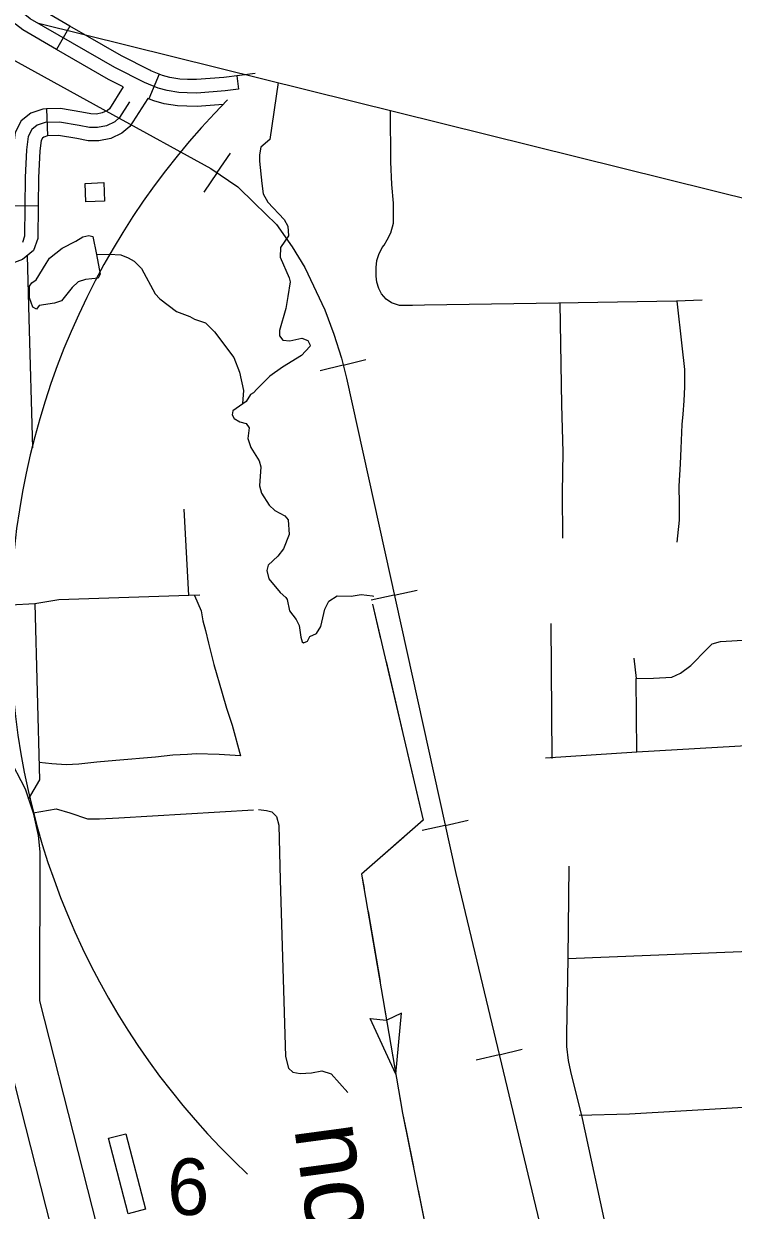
# Model space of a CAD drawing. Extents: x 1671357 to 13005564, y 567358 to 14261451.
# Drawn here: x 12758300.259 to 12758301.586, y 14259942.041 to 14259944.26 of the extents above; entities that cross this region are included whole.
import ezdxf

# ---------------------------------------------------------------- set-up
doc = ezdxf.new("R2010")
doc.units = 0
for name, color, linetype in [('15', 7, 'Continuous'), ('31', 7, 'Continuous'), ('32', 7, 'Continuous'), ('35', 7, 'Continuous'), ('40', 7, 'Continuous'), ('43', 7, 'Continuous'), ('5', 7, 'Continuous'), ('56', 7, 'Continuous'), ('63', 7, 'Continuous'), ('Default', 7, 'Continuous')]:
    doc.layers.add(name, color=color, linetype=linetype)

msp = doc.modelspace()

# ---------------------------------------------------------------- linework, layer by layer
at = {"layer": '15'}
for points in [[(12758299.593, 14259943.9275), (12758299.6236, 14259943.8747), (12758299.6719, 14259943.806), (12758299.8204, 14259943.6294), (12758299.8655, 14259943.5569), (12758300.0827, 14259943.1633), (12758300.2306, 14259942.8901), (12758300.2619, 14259942.8294), (12758300.2768, 14259942.7845), (12758300.2866, 14259942.742), (12758300.2893, 14259942.7116), (12758300.2887, 14259942.4326), (12758300.6474, 14259941.0247)], [(12758300.5675, 14259941.0004), (12758300.2052, 14259942.4222), (12758300.2058, 14259942.7081), (12758300.204, 14259942.7289), (12758300.1964, 14259942.7619), (12758300.1847, 14259942.7969), (12758300.1568, 14259942.8511), (12758300.0094, 14259943.1233), (12758299.7935, 14259943.5146), (12758299.7527, 14259943.5802), (12758299.6057, 14259943.7551), (12758299.5532, 14259943.8296), (12758299.5425, 14259943.8482), (12758299.5157, 14259943.9046)]]:
    msp.add_lwpolyline(points, dxfattribs=at)
at = {"layer": '31'}
for points in [[(12758301.2453, 14259943.1384), (12758301.2468, 14259942.8858)], [(12758301.4006, 14259943.0738), (12758301.4045, 14259943.0354), (12758301.4372, 14259943.0364), (12758301.4715, 14259943.0382), (12758301.4876, 14259943.0453), (12758301.507, 14259943.0599), (12758301.5378, 14259943.0907), (12758301.5467, 14259943.1004), (12758301.5625, 14259943.1048), (12758301.7611, 14259943.1166), (12758301.7694, 14259943.117), (12758301.7785, 14259943.115), (12758301.7847, 14259943.1113), (12758301.7892, 14259943.0997), (12758301.794, 14259942.9863), (12758302.0259, 14259942.9248)], [(12758301.2352, 14259942.8874), (12758301.4057, 14259942.8987), (12758301.4045, 14259943.0354)], [(12758301.4057, 14259942.8987), (12758301.7828, 14259942.9205), (12758301.7937, 14259942.924), (12758301.7951, 14259942.9294), (12758301.7954, 14259942.9391), (12758301.794, 14259942.9863)], [(12758300.2768, 14259942.7845), (12758300.3202, 14259942.792), (12758300.3459, 14259942.7844), (12758300.3785, 14259942.7734), (12758300.4012, 14259942.7734), (12758300.4372, 14259942.7752), (12758300.6892, 14259942.7902)], [(12758301.2791, 14259942.6845), (12758301.277, 14259942.5122), (12758301.2743, 14259942.3704)], [(12758301.277, 14259942.5122), (12758302.0346, 14259942.5427)], [(12758301.2743, 14259942.3704), (12758301.2746, 14259942.3478), (12758301.2777, 14259942.3215), (12758301.2816, 14259942.3005), (12758301.3037, 14259942.213), (12758301.3492, 14259942.0021)]]:
    msp.add_lwpolyline(points, dxfattribs=at)
at = {"layer": '32'}
for p, q in [((12758300.3459, 14259944.255), (12758300.3209, 14259944.2116)), ((12758300.5126, 14259944.1655), (12758300.4936, 14259944.1191)), ((12758300.6577, 14259944.1622), (12758300.661, 14259944.1373)), ((12758300.3022, 14259944.1003), (12758300.3037, 14259944.0502)), ((12758300.2366, 14259943.92), (12758300.2867, 14259943.9194))]:
    msp.add_line(p, q, dxfattribs=at)
for points in [[(12758300.5653, 14259944.1306), (12758300.5492, 14259944.131), (12758300.5274, 14259944.1345), (12758300.5108, 14259944.1391), (12758300.485, 14259944.1498), (12758300.43, 14259944.1776), (12758300.2715, 14259944.269), (12758300.2612, 14259944.2769), (12758300.2535, 14259944.2857), (12758300.2434, 14259944.3027), (12758300.2363, 14259944.3195), (12758300.2335, 14259944.4179), (12758300.2336, 14259944.4531), (12758300.2308, 14259944.4808), (12758300.225, 14259944.514), (12758300.2152, 14259944.5478), (12758300.1987, 14259944.5997), (12758300.1349, 14259944.7499)], [(12758300.3209, 14259944.2116), (12758300.2576, 14259944.2481), (12758300.244, 14259944.2585), (12758300.2331, 14259944.2708), (12758300.221, 14259944.2914), (12758300.2114, 14259944.3141), (12758300.2101, 14259944.3609)], [(12758300.3459, 14259944.255), (12758300.2855, 14259944.2899), (12758300.2783, 14259944.2953), (12758300.2738, 14259944.3005), (12758300.2658, 14259944.3139), (12758300.2612, 14259944.3248), (12758300.2601, 14259944.3624)], [(12758300.4974, 14259944.1717), (12758300.4954, 14259944.1725), (12758300.442, 14259944.1996), (12758300.3459, 14259944.255)], [(12758300.4455, 14259944.1417), (12758300.4181, 14259944.1555), (12758300.3209, 14259944.2116)], [(12758300.6924, 14259944.1667), (12758300.6337, 14259944.159), (12758300.5824, 14259944.1552), (12758300.5659, 14259944.1556), (12758300.5515, 14259944.156), (12758300.5327, 14259944.159), (12758300.519, 14259944.1628), (12758300.4974, 14259944.1717)], [(12758300.4455, 14259944.1417), (12758300.4198, 14259944.1008), (12758300.4159, 14259944.0976), (12758300.4061, 14259944.0929), (12758300.3953, 14259944.0907), (12758300.3848, 14259944.0909), (12758300.3678, 14259944.0941), (12758300.3281, 14259944.101), (12758300.3022, 14259944.1003)], [(12758300.661, 14259944.1373), (12758300.6363, 14259944.1341), (12758300.583, 14259944.1301), (12758300.5653, 14259944.1306)], [(12758300.4573, 14259944.1134), (12758300.4388, 14259944.0841), (12758300.4295, 14259944.0763), (12758300.4141, 14259944.069), (12758300.3976, 14259944.0656), (12758300.3822, 14259944.0659), (12758300.3633, 14259944.0695), (12758300.3263, 14259944.0759), (12758300.2996, 14259944.0751), (12758300.2848, 14259944.0701), (12758300.2745, 14259944.062), (12758300.2677, 14259944.0486), (12758300.2644, 14259944.024), (12758300.2623, 14259943.972), (12758300.2609, 14259943.8623), (12758300.2568, 14259943.8508)], [(12758300.4912, 14259944.1201), (12758300.4579, 14259944.0674), (12758300.4431, 14259944.0551), (12758300.4221, 14259944.045), (12758300.3998, 14259944.0405), (12758300.3796, 14259944.0409), (12758300.3589, 14259944.0448), (12758300.3245, 14259944.0508), (12758300.3037, 14259944.0502)], [(12758300.6321, 14259944.1087), (12758300.5836, 14259944.1051), (12758300.5646, 14259944.1056), (12758300.547, 14259944.1061), (12758300.522, 14259944.11), (12758300.5026, 14259944.1154), (12758300.4912, 14259944.1201)], [(12758300.3021, 14259944.1003), (12758300.2952, 14259944.1001), (12758300.2727, 14259944.0925), (12758300.2547, 14259944.0782), (12758300.2435, 14259944.0562), (12758300.2394, 14259944.0262), (12758300.2373, 14259943.9727), (12758300.2366, 14259943.92)], [(12758301.5283, 14259943.7426), (12758301.4803, 14259943.741), (12758301.2592, 14259943.7371), (12758301.0086, 14259943.7335), (12758300.9863, 14259943.733), (12758300.975, 14259943.7326), (12758300.9623, 14259943.7329), (12758300.9474, 14259943.7377), (12758300.9372, 14259943.7444), (12758300.9285, 14259943.7545), (12758300.9235, 14259943.7644), (12758300.92, 14259943.7767), (12758300.9183, 14259943.7877), (12758300.9187, 14259943.8038), (12758300.9196, 14259943.8172), (12758300.9232, 14259943.8284), (12758300.9298, 14259943.841), (12758300.9333, 14259943.8458), (12758300.939, 14259943.8554), (12758300.9458, 14259943.869), (12758300.9509, 14259943.887), (12758300.9512, 14259943.8987), (12758300.9506, 14259943.9242), (12758300.948, 14259943.9593), (12758300.9459, 14259944.0014), (12758300.9456, 14259944.0973)], [(12758300.3041, 14259944.0502), (12758300.2969, 14259944.0478), (12758300.2943, 14259944.0457), (12758300.292, 14259944.0411), (12758300.2894, 14259944.0219), (12758300.2873, 14259943.9713), (12758300.2867, 14259943.9194)], [(12758300.2867, 14259943.9194), (12758300.2859, 14259943.8578), (12758300.2779, 14259943.8355), (12758300.2569, 14259943.8191), (12758300.2369, 14259943.8115), (12758300.2092, 14259943.8054), (12758300.1544, 14259943.8069)], [(12758301.2675, 14259943.298), (12758301.2669, 14259943.3825), (12758301.2685, 14259943.4589), (12758301.2658, 14259943.5473), (12758301.2628, 14259943.7375)], [(12758301.4813, 14259943.2906), (12758301.4829, 14259943.3024), (12758301.4856, 14259943.3313), (12758301.4855, 14259943.3618), (12758301.4854, 14259943.3953), (12758301.4879, 14259943.4366), (12758301.4886, 14259943.4658), (12758301.491, 14259943.5101), (12758301.4924, 14259943.5299), (12758301.4945, 14259943.5545), (12758301.4959, 14259943.5807), (12758301.4958, 14259943.6135), (12758301.4909, 14259943.6572), (12758301.4811, 14259943.741)], [(12758300.5681, 14259943.1904), (12758300.5595, 14259943.3522)], [(12758300.5887, 14259943.1916), (12758300.5681, 14259943.1904), (12758300.325, 14259943.1824), (12758300.2802, 14259943.1751), (12758300.2345, 14259943.1724)], [(12758300.2802, 14259943.1751), (12758300.2892, 14259942.846), (12758300.2677, 14259942.8096)], [(12758300.5789, 14259943.1907), (12758300.5913, 14259943.1618), (12758300.5946, 14259943.1432), (12758300.5993, 14259943.1253), (12758300.6048, 14259943.1016), (12758300.6148, 14259943.0618), (12758300.6307, 14259943.008), (12758300.6387, 14259942.9798), (12758300.6492, 14259942.948), (12758300.6648, 14259942.8907)], [(12758300.6648, 14259942.8907), (12758300.6251, 14259942.8932), (12758300.582, 14259942.8944), (12758300.5656, 14259942.8932), (12758300.5383, 14259942.8919), (12758300.5057, 14259942.8885), (12758300.4315, 14259942.8819), (12758300.3962, 14259942.8793), (12758300.3623, 14259942.8752), (12758300.3387, 14259942.874), (12758300.3119, 14259942.8761), (12758300.2883, 14259942.8787)], [(12758300.6983, 14259942.7907), (12758300.7134, 14259942.789), (12758300.7235, 14259942.7861), (12758300.7323, 14259942.7778), (12758300.7363, 14259942.7615), (12758300.739, 14259942.6591)], [(12758300.739, 14259942.6591), (12758300.7489, 14259942.3291), (12758300.7544, 14259942.3072), (12758300.7624, 14259942.2995), (12758300.7761, 14259942.297), (12758300.7978, 14259942.2982), (12758300.8167, 14259942.302), (12758300.8346, 14259942.2963), (12758300.8657, 14259942.2617)], [(12758301.3925, 14259942.2218), (12758301.8298, 14259942.2469), (12758301.9275, 14259942.249), (12758302.043, 14259942.2587)], [(12758301.2984, 14259942.2191), (12758301.3925, 14259942.2218)]]:
    msp.add_lwpolyline(points, dxfattribs=at)
at = {"layer": '35'}
for points in [[(12758300.735, 14259944.1496), (12758300.7198, 14259944.0431), (12758300.7027, 14259944.0287), (12758300.7006, 14259944.0148), (12758300.7005, 14259944.0024), (12758300.7049, 14259943.961), (12758300.7074, 14259943.9417), (12758300.7157, 14259943.9263), (12758300.7465, 14259943.8938), (12758300.753, 14259943.8813), (12758300.7545, 14259943.863), (12758300.7397, 14259943.8412), (12758300.7391, 14259943.8234), (12758300.7555, 14259943.7846), (12758300.7575, 14259943.7773), (12758300.753, 14259943.7499), (12758300.7493, 14259943.7273), (12758300.7376, 14259943.6863), (12758300.7377, 14259943.6762), (12758300.7438, 14259943.6678), (12758300.7572, 14259943.6667), (12758300.7797, 14259943.672), (12758300.7909, 14259943.6671), (12758300.7949, 14259943.6589), (12758300.7947, 14259943.6562), (12758300.7787, 14259943.6391), (12758300.7436, 14259943.6175), (12758300.7196, 14259943.6007), (12758300.6956, 14259943.5762), (12758300.6892, 14259943.5693), (12758300.6833, 14259943.5667), (12758300.6752, 14259943.5532), (12758300.6505, 14259943.5358), (12758300.6492, 14259943.5287), (12758300.6531, 14259943.5218), (12758300.6638, 14259943.5155)], [(12758300.3957, 14259943.8279), (12758300.4022, 14259943.7913), (12758300.3989, 14259943.7841), (12758300.3749, 14259943.7817), (12758300.3614, 14259943.7768), (12758300.3502, 14259943.7663), (12758300.3299, 14259943.7416), (12758300.3167, 14259943.7374), (12758300.2882, 14259943.7328), (12758300.2834, 14259943.7262), (12758300.2763, 14259943.7299), (12758300.2705, 14259943.7471), (12758300.2703, 14259943.7689), (12758300.2747, 14259943.7751), (12758300.2828, 14259943.7808), (12758300.3012, 14259943.8111), (12758300.3074, 14259943.8214), (12758300.3314, 14259943.8402), (12758300.3568, 14259943.8534), (12758300.3702, 14259943.8613), (12758300.3811, 14259943.8638), (12758300.3889, 14259943.8618), (12758300.3957, 14259943.8279)], [(12758300.3957, 14259943.8279), (12758300.419, 14259943.8285), (12758300.4411, 14259943.8278), (12758300.4544, 14259943.822), (12758300.466, 14259943.8155), (12758300.4799, 14259943.802), (12758300.5053, 14259943.7548), (12758300.5137, 14259943.7451), (12758300.5451, 14259943.7216), (12758300.5702, 14259943.7123), (12758300.5785, 14259943.7073), (12758300.5845, 14259943.7056), (12758300.5995, 14259943.7002), (12758300.6159, 14259943.6834), (12758300.6526, 14259943.6354), (12758300.6632, 14259943.608), (12758300.6706, 14259943.5738), (12758300.6683, 14259943.5496)], [(12758300.6638, 14259943.5155), (12758300.6756, 14259943.512), (12758300.6809, 14259943.5042), (12758300.6785, 14259943.484), (12758300.6842, 14259943.4675), (12758300.6996, 14259943.4427), (12758300.7031, 14259943.4314), (12758300.7003, 14259943.3954), (12758300.7042, 14259943.3819), (12758300.7182, 14259943.3593), (12758300.7289, 14259943.3497), (12758300.7477, 14259943.3395), (12758300.7537, 14259943.332), (12758300.7559, 14259943.3046), (12758300.7453, 14259943.2781), (12758300.7346, 14259943.2639), (12758300.7166, 14259943.2473), (12758300.714, 14259943.2372), (12758300.718, 14259943.2216), (12758300.7388, 14259943.196), (12758300.7496, 14259943.1871), (12758300.7521, 14259943.1832), (12758300.7566, 14259943.1622), (12758300.769, 14259943.146), (12758300.7745, 14259943.1348), (12758300.7774, 14259943.1129), (12758300.7798, 14259943.1042), (12758300.7825, 14259943.1023), (12758300.7901, 14259943.1053), (12758300.7944, 14259943.1142), (12758300.8069, 14259943.1195), (12758300.8153, 14259943.1326), (12758300.8226, 14259943.1651), (12758300.8297, 14259943.1801), (12758300.8453, 14259943.1901), (12758300.872, 14259943.1896), (12758300.8902, 14259943.1927), (12758300.9117, 14259943.1903), (12758300.9142, 14259943.1896)]]:
    msp.add_lwpolyline(points, dxfattribs=at)
at = {"layer": '40'}
for p, q in [((12758300.621, 14259943.9812), (12758300.6461, 14259944.0175)), ((12758300.621, 14259943.9812), (12758300.5959, 14259943.945)), ((12758300.8566, 14259943.6214), (12758300.8138, 14259943.6107)), ((12758300.8566, 14259943.6214), (12758300.8994, 14259943.6321)), ((12758300.9524, 14259943.1912), (12758300.9954, 14259943.2008)), ((12758300.9524, 14259943.1912), (12758300.9094, 14259943.1817)), ((12758301.0475, 14259942.7609), (12758301.0045, 14259942.7514)), ((12758301.0475, 14259942.7609), (12758301.0906, 14259942.7705)), ((12758301.1487, 14259942.332), (12758301.1058, 14259942.3217)), ((12758301.1487, 14259942.332), (12758301.1915, 14259942.3423))]:
    msp.add_line(p, q, dxfattribs=at)
msp.add_lwpolyline([(12758297.2486, 14259948.9822), (12758299.1441, 14259944.971), (12758299.1968, 14259944.8707), (12758299.2377, 14259944.8117), (12758299.2719, 14259944.7683), (12758299.3027, 14259944.7371), (12758299.3394, 14259944.7048), (12758299.37, 14259944.6783), (12758299.4523, 14259944.6262), (12758300.4257, 14259944.0898), (12758300.6095, 14259943.9892), (12758300.6598, 14259943.9544), (12758300.6911, 14259943.9243), (12758300.7319, 14259943.8844), (12758300.7614, 14259943.8425), (12758300.7854, 14259943.8036), (12758300.8228, 14259943.7248), (12758300.8391, 14259943.6795), (12758300.8534, 14259943.6342), (12758300.8627, 14259943.5971), (12758301.0674, 14259942.6711), (12758301.4683, 14259940.9978)], dxfattribs=at)
at = {"layer": '43'}
for p, q in [((12758300.9555, 14259942.2955), (12758300.9075, 14259942.3996)), ((12758300.9075, 14259942.3996), (12758300.9379, 14259942.3968)), ((12758300.966, 14259942.4096), (12758300.9383, 14259942.3969)), ((12758300.9555, 14259942.2955), (12758300.966, 14259942.4096))]:
    msp.add_line(p, q, dxfattribs=at)
for points in [[(12758300.9118, 14259943.1742), (12758301.0066, 14259942.7707), (12758300.8913, 14259942.67), (12758300.9679, 14259942.2228), (12758301.0188, 14259941.9701), (12758301.025, 14259941.9041)], [(12758300.9118, 14259943.1742), (12758300.9269, 14259943.1099)], [(12758300.937, 14259943.067), (12758300.9672, 14259942.9383)], [(12758300.9773, 14259942.8954), (12758301.0066, 14259942.7707), (12758301.0034, 14259942.768)], [(12758300.9702, 14259942.739), (12758300.8913, 14259942.67), (12758300.8959, 14259942.643)], [(12758300.9033, 14259942.5996), (12758300.9257, 14259942.4693)], [(12758300.9331, 14259942.4259), (12758300.9555, 14259942.2955)], [(12758300.9629, 14259942.2521), (12758300.9679, 14259942.2228), (12758300.9751, 14259942.1871)], [(12758300.9751, 14259942.1871), (12758300.9881, 14259942.1223)], [(12758300.9968, 14259942.0791), (12758301.0188, 14259941.9701), (12758301.0207, 14259941.9492)]]:
    msp.add_lwpolyline(points, dxfattribs=at)
at = {"layer": '5'}
for points in [[(12758300.2657, 14259943.826), (12758300.269, 14259943.7085)], [(12758300.269, 14259943.7085), (12758300.2757, 14259943.4668)]]:
    msp.add_lwpolyline(points, dxfattribs=at)
at = {"layer": '56'}
for points in [[(12758300.3756, 14259943.9265), (12758300.3741, 14259943.9612), (12758300.4089, 14259943.9627), (12758300.4104, 14259943.9279)], [(12758300.4181, 14259942.1761), (12758300.4504, 14259942.1845), (12758300.4871, 14259942.0431), (12758300.4547, 14259942.0348)]]:
    msp.add_lwpolyline(points, close=True, dxfattribs=at)
at = {"layer": '63'}
msp.add_arc((12758301.6325, 14259943.1312), 1.3986, 135.1742, 226.9585, dxfattribs=at)
at = {"layer": 'Default'}
msp.add_lwpolyline([(12758300.287, 14259944.2608), (12758302.6359, 14259943.6777), (12758302.1816, 14259944.3171)], dxfattribs=at)

# ---------------------------------------------------------------- texts
at = {"layer": '43'}
msp.add_text('Bayou', height=0.14102, rotation=97.6642, dxfattribs=at).set_placement((12758300.9437, 14259941.6801))
at = {"layer": '56'}
msp.add_text('6', height=0.1058, dxfattribs=at).set_placement((12758300.5278, 14259942.0325))

doc.saveas('drawing.dxf')
